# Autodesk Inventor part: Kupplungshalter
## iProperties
Created: 2004-10
Part Number: Kupplungshalter
Material: Aluminium
Document SubType Name: Modellieren
Designer: Ulrich
Control State: 0
Master: False
Checked Out: False
Shininess: 20.0
Angle Display Precision: 2
Document Length Units: 11269
Document Angle Units: 11279
Document Time Units: 11290
Document Mass Units: 11283
Document Length Units Precision: 3
Document Angle Units Precision: 2
Density: 0.0
Volumn: 0.0
Area: 0.0
PropertySet Name: Model Information
Author: Ulrich
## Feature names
1. Grundkörper [Extrusion]
2. Durchgangsbohrung M4 [Hole]
3. Gewinde M4 [Hole]
4. Stiftloch d2 [Hole]
